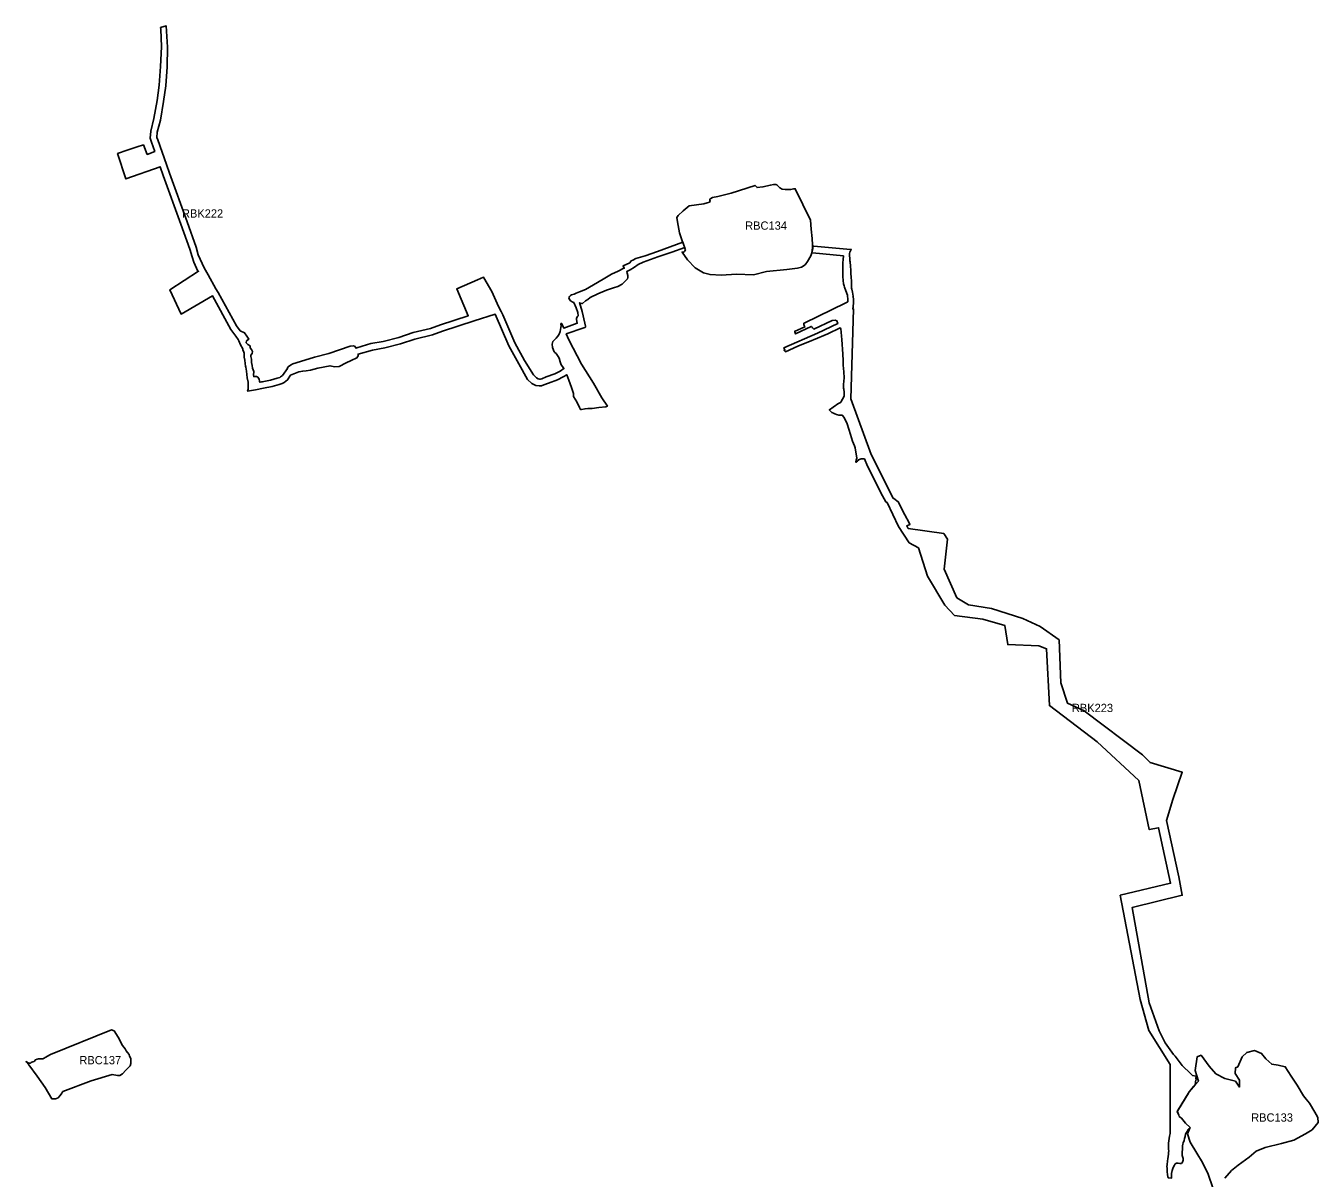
# Model space of a CAD drawing. Extents: x -559776 to -467147, y -1204122 to -1132159.
# Drawn here: x -532589 to -524774, y -1195807 to -1188837 of the extents above; entities that cross this region are included whole.
import ezdxf

# ---------------------------------------------------------------- set-up
doc = ezdxf.new("R2010")
doc.units = 0
doc.layers.add('regionalni_biocentrum_biokoridor', color=7, linetype='Continuous')

msp = doc.modelspace()

# ---------------------------------------------------------------- linework, layer by layer
at = {"layer": 'regionalni_biocentrum_biokoridor'}
for points in [[(-528616.16, -1190145.84), (-528607.53, -1190169.12), (-528604.28, -1190178.21), (-528682.64, -1190205.4), (-528766.75, -1190234.03), (-528855.63, -1190266.49), (-528885.25, -1190280.81), (-528907.24, -1190297.04), (-528934.95, -1190313.26), (-528955.24, -1190322.91), (-528952.15, -1190333.31), (-528949.28, -1190347.63), (-528949.28, -1190359.08), (-528951.2, -1190367.67), (-528961.71, -1190378.84), (-528981.78, -1190398.89), (-529008.54, -1190413.21), (-529034.34, -1190421.8), (-529077.35, -1190435.16), (-529130.87, -1190458.07), (-529176.74, -1190480.03), (-529190.12, -1190491.48), (-529204.46, -1190499.12), (-529221.66, -1190515.35), (-529229.31, -1190515.35), (-529237.91, -1190514.39), (-529239.82, -1190510.57), (-529224.53, -1190564.03), (-529209.24, -1190635.62), (-529204.22, -1190653.06), (-529204.22, -1190658.36), (-529207.26, -1190661.39), (-529214.84, -1190663.67), (-529320.91, -1190700.22), (-529305.17, -1190736.4), (-529229.33, -1190882.56), (-529156.51, -1190998.43), (-529104.94, -1191087.8), (-529071.57, -1191136.27), (-529082.19, -1191140.81), (-529123.9, -1191145.35), (-529164.86, -1191150.65), (-529190.65, -1191151.41), (-529206.57, -1191152.93), (-529227.81, -1191156.71), (-529235.39, -1191156.71), (-529240.7, -1191145.35), (-529256.63, -1191110.52), (-529276.35, -1191077.95), (-529277.11, -1191059.78), (-529290, -1191023.42), (-529305.17, -1190980.26), (-529318.26, -1190947.3), (-529338.79, -1190959.96), (-529374.1, -1190977.58), (-529427.99, -1190997.86), (-529455.82, -1191008.97), (-529470.72, -1191013.44), (-529484.46, -1191013.44), (-529505.4, -1191011.54), (-529529.93, -1190999.63), (-529555.47, -1190976.27), (-529607.77, -1190881.67), (-529667.8, -1190772.2), (-529750.97, -1190580.05), (-529877.6, -1190620.68), (-530068.88, -1190682.68), (-530130.75, -1190705.13), (-530236.22, -1190731.1), (-530322.93, -1190759.59), (-530418.57, -1190784.73), (-530493.66, -1190798.13), (-530579.74, -1190822.43), (-530579.74, -1190833.32), (-530586.89, -1190845.05), (-530621.75, -1190860.97), (-530651.25, -1190876.05), (-530694.15, -1190897), (-530721.87, -1190898.67), (-530749.58, -1190892.81), (-530822.87, -1190907.89), (-530868.46, -1190919.62), (-530894.38, -1190923.81), (-530914.94, -1190924.65), (-530937.29, -1190928.84), (-530968.04, -1190941.41), (-530988.24, -1190948.95), (-531006.12, -1190978.27), (-531027.57, -1190995.03), (-531038.3, -1191000.05), (-531056.53, -1191006.76), (-531099.44, -1191018.49), (-531152.18, -1191029.38), (-531201.24, -1191038.4), (-531247.82, -1191046.55), (-531245.65, -1191034.83), (-531245.2, -1191022.57), (-531244.06, -1190992.18), (-531250.21, -1190965.26), (-531253.8, -1190926), (-531259.64, -1190900.68), (-531259.91, -1190895.48), (-531263.32, -1190878.71), (-531265.17, -1190858.77), (-531268.16, -1190841.02), (-531268.16, -1190816.52), (-531271.17, -1190811.03), (-531277.62, -1190796.13), (-531277.18, -1190790.32), (-531291.6, -1190766.01), (-531301.82, -1190742.05), (-531305.9, -1190734.39), (-531318.37, -1190714.22), (-531348.91, -1190673.93), (-531461.18, -1190468.95), (-531650.66, -1190580.02), (-531718.97, -1190434.49), (-531544.74, -1190321.51), (-531548.26, -1190320.5), (-531572.67, -1190266.55), (-531584.17, -1190234.21), (-531597.81, -1190188.19), (-531651.95, -1190035.93), (-531758.31, -1189741.88), (-531776.91, -1189688.95), (-531984.05, -1189762.53), (-532034.29, -1189609.14), (-531977.17, -1189588.73), (-531915.01, -1189569.25), (-531878.13, -1189556.6), (-531855.4, -1189614.41), (-531809.42, -1189596.44), (-531829.29, -1189539.88), (-531837.6, -1189516.25), (-531833.81, -1189473.68), (-531814.33, -1189398), (-531795.61, -1189287.67), (-531782.25, -1189195.01), (-531774.21, -1189081.93), (-531768.84, -1188963.73), (-531772.19, -1188857.22), (-531774.81, -1188847.77), (-531739.81, -1188836.75), (-531731.71, -1188966.6), (-531734.27, -1189084.25), (-531742.45, -1189199.29), (-531756.09, -1189293.87), (-531775.17, -1189406.35), (-531794.26, -1189480.48), (-531796.99, -1189511.16), (-531791.43, -1189526.96), (-531739.22, -1189675.56), (-531720.64, -1189728.44), (-531614.3, -1190022.42), (-531559.76, -1190175.8), (-531546.13, -1190221.81), (-531509.89, -1190299.66), (-531486.72, -1190343.02), (-531439.8, -1190427.96), (-531426.73, -1190449.34), (-531315.46, -1190651.85), (-531292.68, -1190681.89), (-531266.59, -1190693.56), (-531252.29, -1190712.83), (-531241.57, -1190732.1), (-531254.08, -1190742.16), (-531255.87, -1190754.72), (-531246.03, -1190763.94), (-531232.63, -1190772.32), (-531233.52, -1190784.05), (-531223.69, -1190794.94), (-531218.33, -1190805.83), (-531221.01, -1190819.24), (-531228.16, -1190829.29), (-531228.16, -1190837.67), (-531225.48, -1190853.59), (-531223.69, -1190872.86), (-531220.11, -1190890.46), (-531219.22, -1190908.05), (-531210.9, -1190927.91), (-531212.72, -1190949.79), (-531210.68, -1190958.69), (-531208.85, -1190958.57), (-531194.55, -1190957.61), (-531185.36, -1190962.4), (-531178.21, -1190973.9), (-531175.14, -1190985.4), (-531174.02, -1190992.79), (-531163.95, -1190990.87), (-531159.84, -1190990.12), (-531108.77, -1190979.57), (-531068.73, -1190968.62), (-531053.71, -1190963.1), (-531048.63, -1190960.72), (-531036.48, -1190951.23), (-531007.63, -1190909.77), (-531007.9, -1190908.73), (-531003.44, -1190899.51), (-530989.13, -1190889.46), (-530973.94, -1190881.08), (-530928.35, -1190866.84), (-530842.54, -1190841.7), (-530756.73, -1190818.24), (-530627.12, -1190773.83), (-530608.34, -1190771.32), (-530596.72, -1190777.19), (-530593.59, -1190785.54), (-530555.21, -1190773.94), (-530502.63, -1190759.1), (-530427.18, -1190745.63), (-530334.26, -1190721.21), (-530247.26, -1190692.63), (-530142.38, -1190666.8), (-530081.88, -1190644.84), (-529913.51, -1190590.27), (-529982.69, -1190427.48), (-529858.45, -1190373.73), (-529857.52, -1190373.82), (-529821.65, -1190356.37), (-529821.04, -1190357.54), (-529819.74, -1190360), (-529771.96, -1190442.75), (-529729.91, -1190533.43), (-529715.09, -1190563.94), (-529704.16, -1190584.29), (-529631.76, -1190754.72), (-529573.36, -1190861.23), (-529517.99, -1190947.6), (-529501.61, -1190965.11), (-529490.99, -1190972.68), (-529482.65, -1190973.44), (-529476.58, -1190973.44), (-529469, -1190971.17), (-529442.45, -1190960.57), (-529390.12, -1190940.87), (-529358.26, -1190924.97), (-529334.65, -1190910.41), (-529337.03, -1190905.28), (-529351.44, -1190886.35), (-529356.75, -1190868.17), (-529362.81, -1190847.72), (-529368.88, -1190836.36), (-529374.19, -1190831.06), (-529381.02, -1190818.94), (-529389.36, -1190812.89), (-529393.91, -1190808.34), (-529404.53, -1190782.59), (-529405.29, -1190762.9), (-529401.5, -1190745.48), (-529394.67, -1190737.15), (-529382.53, -1190725.79), (-529372.67, -1190714.43), (-529364.33, -1190701.56), (-529356.75, -1190686.41), (-529352.95, -1190661.42), (-529352.2, -1190651.57), (-529353.71, -1190643.24), (-529352.95, -1190637.94), (-529349.16, -1190636.43), (-529345.37, -1190644), (-529336.38, -1190664.68), (-529253.89, -1190635.81), (-529259.89, -1190612.71), (-529259.89, -1190606.03), (-529257.02, -1190600.3), (-529253.2, -1190594.57), (-529248.42, -1190590.76), (-529251.29, -1190570.71), (-529260.84, -1190543.03), (-529275.18, -1190511.05), (-529281.87, -1190507.71), (-529295.25, -1190499.12), (-529303.85, -1190488.62), (-529304.81, -1190480.98), (-529301.94, -1190474.3), (-529295.25, -1190467.62), (-529289.51, -1190464.75), (-529273.27, -1190459.03), (-529261.8, -1190453.3), (-529240.77, -1190445.66), (-529205.41, -1190431.34), (-529155.72, -1190402.71), (-529098.38, -1190368.34), (-529047.72, -1190338.75), (-529007.58, -1190320.9), (-528973.18, -1190302.76), (-528970.59, -1190303.5), (-528977, -1190287.49), (-528937.24, -1190271.26), (-528928.64, -1190258.85), (-528919.09, -1190253.13), (-528899.97, -1190243.58), (-528844.54, -1190227.35), (-528769.04, -1190202.53)], [(-528604.28, -1190178.21), (-528607.53, -1190169.12), (-528616.16, -1190145.84), (-528617.08, -1190143.35), (-528636.2, -1190087.98), (-528647.67, -1190022.12), (-528651.49, -1189995.39), (-528644.8, -1189982.98), (-528614.22, -1189955.3), (-528577.9, -1189924.75), (-528488.06, -1189913.3), (-528468.95, -1189907.57), (-528454.61, -1189903.75), (-528450.79, -1189897.07), (-528451.75, -1189891.34), (-528451.75, -1189884.66), (-528446.97, -1189881.8), (-528435.5, -1189876.07), (-528403.4, -1189868.78), (-528324.41, -1189847.9), (-528179.22, -1189801.51), (-528166.44, -1189815.42), (-528131.59, -1189810.79), (-528086.29, -1189800.35), (-528066.54, -1189796.87), (-528053.77, -1189795.71), (-528046.8, -1189799.19), (-528028.21, -1189816.58), (-528014.27, -1189824.7), (-527996.85, -1189825.86), (-527963.16, -1189825.86), (-527945.74, -1189823.54), (-527936.45, -1189822.38), (-527843.52, -1190012.6), (-527838.87, -1190067.11), (-527833.07, -1190122.79), (-527831.9, -1190162.22), (-527832.34, -1190175.77), (-527833.07, -1190198.18), (-527837.79, -1190215.71), (-527841.2, -1190228.34), (-527860.94, -1190263.13), (-527876.04, -1190282.85), (-527898.11, -1190296.77), (-527922.51, -1190302.57), (-527986.39, -1190310.69), (-528110.68, -1190323.44), (-528188.51, -1190342), (-528290.73, -1190339.68), (-528383.65, -1190344.32), (-528451.03, -1190340.84), (-528489.98, -1190331.4), (-528541.58, -1190299.9), (-528588.41, -1190251.22), (-528619.95, -1190205.4), (-528612.31, -1190205.4), (-528605.62, -1190201.58), (-528602.75, -1190196.81), (-528599.88, -1190192.03), (-528600.84, -1190187.26), (-528602.75, -1190182.49)], [(-527590.47, -1190447.71), (-527585.42, -1190472.49), (-527587.14, -1190472.24), (-527584.99, -1190476.22), (-527583.87, -1190489.4), (-527582.82, -1190501.81), (-527583.24, -1190506.29), (-527586.39, -1190539.59), (-527586.87, -1190544.7), (-527587.5, -1190551.33), (-527583.25, -1190549.98), (-527600.04, -1191092.96), (-527476.89, -1191428.82), (-527344.62, -1191693.36), (-527338.73, -1191695.94), (-527312.66, -1191715.88), (-527273.2, -1191795.26), (-527246.07, -1191843.95), (-527242.2, -1191852.1), (-527261.23, -1191860.13), (-527252.98, -1191876.63), (-527037.47, -1191907.42), (-527014.8, -1191941.01), (-527034.39, -1192122.93), (-526958.83, -1192296.46), (-526888.86, -1192338.44), (-526748.91, -1192360.83), (-526558.59, -1192422.41), (-526455.03, -1192469.99), (-526340.28, -1192551.15), (-526329.09, -1192811.45), (-526289.9, -1192934.6), (-526189.14, -1192979.38), (-525836.49, -1193245.27), (-525788.91, -1193292.85), (-525595.79, -1193351.62), (-525651.77, -1193516.75), (-525690.95, -1193642.7), (-525615.38, -1193984.16), (-525595.79, -1194096.11), (-525898.07, -1194168.88), (-525794.51, -1194745.45), (-525735.73, -1194916.18), (-525698.77, -1194988.62), (-525647.85, -1195058.84), (-525639.12, -1195069.79), (-525596.74, -1195124.71), (-525544.36, -1195175.01), (-525534.06, -1195184.9), (-525511.82, -1195190.46), (-525513.29, -1195204.85), (-525509.8, -1195208.2), (-525514.08, -1195212.56), (-525517.11, -1195242.3), (-525526.41, -1195252.93), (-525551.87, -1195282.02), (-525553.64, -1195284.04), (-525558.38, -1195291.95), (-525624.24, -1195401.71), (-525625.43, -1195403.69), (-525625.26, -1195404.11), (-525624.7, -1195405.51), (-525616.29, -1195426.54), (-525613.4, -1195433.77), (-525600.87, -1195443.87), (-525575.62, -1195473.87), (-525548.19, -1195500.37), (-525549.92, -1195504.45), (-525555.8, -1195509.1), (-525558.8, -1195513.1), (-525562.4, -1195518), (-525570.3, -1195530.7), (-525574.5, -1195537.6), (-525575, -1195540.3), (-525578.3, -1195554.4), (-525581.6, -1195567.8), (-525584.2, -1195579.8), (-525589.1, -1195592.8), (-525592.5, -1195602.2), (-525593.3, -1195611.9), (-525595.3, -1195669.9), (-525590.5, -1195688.2), (-525590.4, -1195698.8), (-525593, -1195710.8), (-525600.4, -1195718.6), (-525610, -1195717.9), (-525620.4, -1195716.7), (-525631, -1195715.8), (-525638.1, -1195720.7), (-525642.4, -1195728.8), (-525647.6, -1195738.2), (-525651.7, -1195748.9), (-525655.5, -1195761.45), (-525660.41, -1195778.4), (-525660.65, -1195787.27), (-525660.98, -1195795.42), (-525659.6, -1195806.1), (-525679.8, -1195804.94), (-525680.28, -1195803.59), (-525681.62, -1195799.8), (-525684.01, -1195784.2), (-525686.28, -1195769.45), (-525686.5, -1195764.96), (-525687.45, -1195745.6), (-525687.92, -1195735.96), (-525686.9, -1195727.22), (-525683.92, -1195701.82), (-525682.43, -1195689.13), (-525680.86, -1195675.71), (-525679.31, -1195662.48), (-525677.65, -1195648.27), (-525677.34, -1195645.66), (-525678.01, -1195629.14), (-525678.63, -1195614.04), (-525679.39, -1195595.2), (-525679.42, -1195594.52), (-525676.92, -1195580.09), (-525674.62, -1195566.87), (-525672.02, -1195551.86), (-525669.47, -1195537.2), (-525668.97, -1195534.3), (-525668.66, -1195520.52), (-525668.14, -1195497.79), (-525667.68, -1195477.75), (-525668.77, -1195118.48), (-525797.31, -1194913.38), (-525850.48, -1194725.85), (-525970.84, -1194096.11), (-525665.76, -1194023.35), (-525738.53, -1193687.48), (-525794.51, -1193698.68), (-525858.88, -1193402), (-526110.78, -1193166.9), (-526399.06, -1192948.59), (-526415.85, -1192604.33), (-526463.43, -1192587.54), (-526650.95, -1192579.14), (-526667.75, -1192464.39), (-526802.09, -1192425.21), (-526972.82, -1192402.82), (-527031.6, -1192341.24), (-527135.15, -1192164.91), (-527191.13, -1191994.18), (-527247.11, -1191963.4), (-527311.48, -1191865.44), (-527380.75, -1191720.95), (-527388.63, -1191716.11), (-527408.77, -1191678.75), (-527499.9, -1191499.29), (-527517.75, -1191456.81), (-527536.6, -1191456.81), (-527553.44, -1191461.92), (-527556.26, -1191464.91), (-527560.07, -1191468.95), (-527562.76, -1191471.8), (-527564.51, -1191473.65), (-527566.23, -1191475.48), (-527568.03, -1191475.72), (-527569.77, -1191475.96), (-527569.52, -1191474.88), (-527566.91, -1191463.44), (-527564.14, -1191451.26), (-527572.58, -1191389.73), (-527578.23, -1191377.6), (-527590.13, -1191348.21), (-527600.89, -1191308.42), (-527621.65, -1191244.46), (-527639.35, -1191205.05), (-527651.27, -1191191.8), (-527653.22, -1191191.69), (-527656.7, -1191191.5), (-527666.88, -1191191.42), (-527672.33, -1191191.38), (-527685.52, -1191186.65), (-527696.56, -1191182.69), (-527705.33, -1191179.55), (-527714.71, -1191176.19), (-527719.29, -1191170.89), (-527727.96, -1191160.84), (-527729.4, -1191159.18), (-527706.5, -1191142.63), (-527705.62, -1191141.99), (-527700.84, -1191138.54), (-527678.89, -1191122.67), (-527665.54, -1191116.09), (-527662.62, -1191114.63), (-527660.34, -1191113.5), (-527639.8, -1191076.2), (-527639.5, -1191052.8), (-527642.9, -1191035.3), (-527643.7, -1191029), (-527643.9, -1191006.6), (-527639.32, -1190964.93), (-527641.42, -1190928.8), (-527645.6, -1190889.3), (-527645.81, -1190860.12), (-527647.7, -1190821.9), (-527655.1, -1190735), (-527656.9, -1190714), (-527658.6, -1190690), (-527660.23, -1190668.48), (-527663.8, -1190664), (-527739.5, -1190699.2), (-527825.6, -1190736.5), (-527836.47, -1190740.95), (-527919.8, -1190775.1), (-527994.7, -1190807.7), (-528003.3, -1190800.6), (-527998.38, -1190800.29), (-527999, -1190798.7), (-528002.83, -1190788.86), (-528004.66, -1190784.15), (-527800.53, -1190696.25), (-527678.67, -1190638.16), (-527684.44, -1190620.11), (-527694.94, -1190618.01), (-527712.83, -1190619.96), (-527823.09, -1190670.98), (-527831.41, -1190662.65), (-527834.22, -1190659.76), (-527838.89, -1190654.96), (-527935.19, -1190699.76), (-527938.93, -1190687.87), (-527939.66, -1190685.57), (-527877.85, -1190657.89), (-527881.5, -1190648.5), (-527883.2, -1190642.6), (-527884.85, -1190637.19), (-527881.27, -1190635.44), (-527630.89, -1190513.19), (-527617.71, -1190505.2), (-527616.95, -1190494.26), (-527620.41, -1190465.95), (-527624.37, -1190455.52), (-527639.03, -1190416.92), (-527640.54, -1190410.15), (-527643.18, -1190398.28), (-527645.25, -1190376.19), (-527648.01, -1190352.71), (-527648.7, -1190325.09), (-527648.2, -1190302.67), (-527648.01, -1190294.02), (-527648.01, -1190269.85), (-527646.63, -1190249.13), (-527644.56, -1190228.42), (-527832.08, -1190210.5), (-527835.64, -1190210.16), (-527830.06, -1190184.76), (-527828.92, -1190177.93), (-527827.44, -1190169.1), (-527824.1, -1190169.31), (-527824.12, -1190169.4), (-527601.13, -1190189.78), (-527595.93, -1190190.25), (-527600.01, -1190193.46), (-527606.38, -1190205.12), (-527607.53, -1190213.32), (-527607.24, -1190219.75), (-527605.84, -1190250.48), (-527604.98, -1190257.76), (-527604.95, -1190257.97), (-527604.24, -1190264), (-527602.83, -1190275.87), (-527602.65, -1190279.1), (-527599.76, -1190326.22), (-527599.37, -1190332.59), (-527598.95, -1190339.38), (-527598.16, -1190352.29), (-527597.48, -1190363.31), (-527596.76, -1190375), (-527596.15, -1190384.93), (-527595.53, -1190395.02), (-527596.1, -1190407.5), (-527596.61, -1190417.57), (-527595.46, -1190423.23), (-527593.97, -1190430.53)], [(-531955.22, -1195083.13), (-531954.58, -1195098.28), (-531955.22, -1195112.79), (-531959.01, -1195126.68), (-531963.43, -1195134.26), (-531984.92, -1195154.46), (-532003.88, -1195175.29), (-532020.94, -1195185.39), (-532034.72, -1195185.2), (-532066.32, -1195180.78), (-532194.61, -1195217.39), (-532365.24, -1195283.67), (-532374.72, -1195298.82), (-532384.2, -1195309.55), (-532394.31, -1195321.54), (-532403.79, -1195325.96), (-532410.74, -1195326.59), (-532418.32, -1195327.22), (-532432.46, -1195326.63), (-532471.53, -1195259.35), (-532520.36, -1195189.45), (-532570.56, -1195122.09), (-532589.21, -1195101.94), (-532570.25, -1195112.04), (-532562.03, -1195111.41), (-532556.34, -1195108.25), (-532553.82, -1195105.73), (-532547.5, -1195103.83), (-532539.28, -1195101.94), (-532531.06, -1195091.21), (-532520.32, -1195086.79), (-532512.74, -1195084.26), (-532504.52, -1195084.9), (-532497.57, -1195084.9), (-532487.46, -1195084.26), (-532479.24, -1195080.48), (-532471.66, -1195076.06), (-532440.69, -1195059.02), (-532070.23, -1194908.91), (-532055.7, -1194915.22), (-532031.05, -1194954.99), (-532003.88, -1195003.59), (-531989.34, -1195024.42), (-531982.39, -1195036.42), (-531974.17, -1195046.52), (-531964.69, -1195057.88), (-531961.53, -1195068.61)]]:
    msp.add_lwpolyline(points, close=True, dxfattribs=at)
msp.add_lwpolyline([(-525411.31, -1195866), (-525437.94, -1195782), (-525473.37, -1195711.75), (-525507, -1195656.37), (-525546.56, -1195588.87), (-525564.37, -1195538.5), (-525549.92, -1195504.45), (-525548.19, -1195500.37), (-525575.62, -1195473.87), (-525600.87, -1195443.87), (-525613.4, -1195433.77), (-525616.29, -1195426.54), (-525625.43, -1195403.69), (-525553.64, -1195284.04), (-525517.11, -1195242.3), (-525497.8, -1195220.23), (-525516.39, -1195156.5), (-525505.81, -1195073.12), (-525482, -1195063.12), (-525433.19, -1195129.37), (-525391.94, -1195175.87), (-525337.94, -1195204.25), (-525274.37, -1195219.62), (-525249.19, -1195255.75), (-525249.75, -1195213.87), (-525275.19, -1195172.87), (-525274.37, -1195140.12), (-525259.31, -1195133), (-525233.31, -1195073.87), (-525205.44, -1195045.87), (-525157.56, -1195035.25), (-525115.62, -1195052.25), (-525088.94, -1195086), (-525054.37, -1195117.5), (-525014.69, -1195124), (-524972.75, -1195133.37), (-524937.69, -1195189.87), (-524899.94, -1195244.87), (-524862.25, -1195308.37), (-524845.69, -1195328.62), (-524826.19, -1195352.5), (-524794.56, -1195407.62), (-524786.19, -1195422.37), (-524776.19, -1195440.12), (-524773.5, -1195471.12), (-524810.19, -1195514.87), (-524849.19, -1195538.87), (-524921.06, -1195577.5), (-524995.94, -1195597.5), (-525093.5, -1195622), (-525148.06, -1195643.75), (-525191.06, -1195679.12), (-525257.12, -1195727.75), (-525297.5, -1195760.62), (-525337, -1195807.62)], dxfattribs=at)

# ---------------------------------------------------------------- texts
for s, p in [('RBK222', (-531644.86, -1189996.73)), ('RBC134', (-528238.95, -1190070.02)), ('RBK223', (-526262.89, -1192987.6)), ('RBC137', (-532265.47, -1195118.06)), ('RBC133', (-525178.56, -1195465))]:
    msp.add_text(s, height=50, dxfattribs=at).set_placement(p)

doc.saveas('drawing.dxf')
